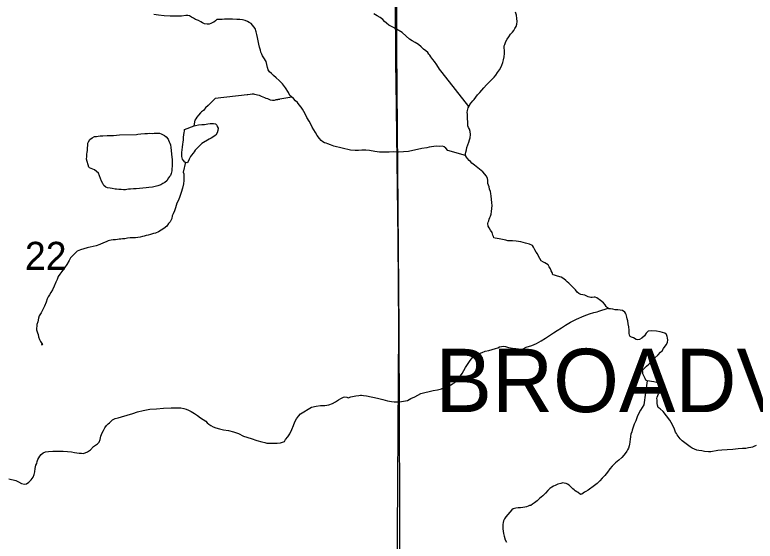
# Model space of a CAD drawing. Extents: x 2010165 to 2382125, y 1060529 to 1407316.
# Drawn here: x 2189541 to 2195389, y 1211343 to 1215496 of the extents above; entities that cross this region are included whole.
import ezdxf

# ---------------------------------------------------------------- set-up
doc = ezdxf.new("R2010")
doc.units = 0
for name, color, linetype in [('GM_X_Corporation_Text', 7, 'Continuous'), ('GM_X_Minor_Lake', 7, 'Continuous'), ('GM_X_Minor_River', 7, 'Continuous'), ('GM_X_Section', 7, 'Continuous'), ('GM_X_Section_Text', 7, 'Continuous'), ('GM_X_State_Route', 7, 'Continuous')]:
    doc.layers.add(name, color=color, linetype=linetype)

msp = doc.modelspace()

# ---------------------------------------------------------------- linework, layer by layer
at = {"layer": 'GM_X_Minor_Lake'}
for points in [[(2191077.5, 1214514.5), (2191017.7, 1214480.5), (2190998.2, 1214459.9), (2190986.4, 1214449.6), (2190976.7, 1214439.3), (2190967, 1214426.9), (2190957.3, 1214414.7), (2190949.5, 1214404.4), (2190936, 1214388), (2190930.2, 1214377.8), (2190918.7, 1214357.4), (2190911.2, 1214339.1), (2190901.5, 1214328.9), (2190883.3, 1214334.4), (2190872.9, 1214346.2), (2190864.6, 1214358), (2190860, 1214377.9), (2190859.7, 1214390), (2190861.2, 1214408.1), (2190862.6, 1214430.2), (2190866, 1214452.4), (2190869.4, 1214474.6), (2190871, 1214490.7), (2190872.5, 1214508.8), (2190874, 1214528.9), (2190877.4, 1214551.1), (2190879, 1214565.2), (2190880.7, 1214579.3), (2190882.3, 1214591.4), (2190957.8, 1214619.5)], [(2190957.8, 1214619.5), (2190967.7, 1214623.7), (2190991.6, 1214628.4), (2191017.6, 1214631.1), (2191039.7, 1214631.6), (2191053.6, 1214634), (2191065.7, 1214634.3), (2191085.6, 1214636.9), (2191101.7, 1214637.3), (2191111.7, 1214637.6), (2191125.8, 1214635.9), (2191136.1, 1214624.1), (2191140.4, 1214614.2), (2191146.8, 1214600.3), (2191145.3, 1214582.2), (2191139.7, 1214564), (2191128.2, 1214545.6), (2191092.7, 1214522.6), (2191077.5, 1214514.5)], [(2190125, 1214293.3), (2190106.6, 1214358.1), (2190110.1, 1214378.3), (2190111.5, 1214398.4), (2190113.2, 1214410.5), (2190114.7, 1214428.6), (2190119.3, 1214482.9), (2190123, 1214493.1), (2190134.5, 1214511.4), (2190152.3, 1214523.9), (2190170, 1214534.4), (2190186, 1214536.9), (2190200, 1214539.3), (2190215.9, 1214541.7), (2190236, 1214542.2), (2190270, 1214543.1), (2190296.1, 1214543.8), (2190322.1, 1214544.5), (2190344.2, 1214545.1), (2190368.2, 1214547.7), (2190503.5, 1214552.5)], [(2190503.5, 1214552.5), (2190512.4, 1214553.5), (2190536.4, 1214556.1), (2190568.4, 1214559), (2190588.4, 1214559.5), (2190606.4, 1214562), (2190626.5, 1214560.5), (2190642.5, 1214561), (2190658.6, 1214561.4), (2190674.6, 1214561.8), (2190684.6, 1214562.1), (2190696.8, 1214556.4), (2190713.1, 1214548.8), (2190723.2, 1214543), (2190737.5, 1214533.3), (2190752, 1214515.6), (2190756.3, 1214505.7), (2190760.6, 1214493.8), (2190767, 1214481.9), (2190771.3, 1214470), (2190773.9, 1214448), (2190782, 1214371.9), (2190784.5, 1214353.9), (2190785, 1214333.8), (2190785.5, 1214315.8), (2190783.9, 1214299.7), (2190782.4, 1214283.6), (2190780.8, 1214265.4), (2190779.2, 1214253.4), (2190775.4, 1214243.2), (2190769.8, 1214229), (2190764.1, 1214218.8), (2190756.3, 1214208.6), (2190742.9, 1214186.1), (2190727.2, 1214173.7), (2190711.4, 1214165.2), (2190693.6, 1214154.7), (2190669.8, 1214146.1), (2190649.8, 1214141.5), (2190630, 1214135), (2190600, 1214132.2), (2190580, 1214129.6), (2190552, 1214126.9), (2190526, 1214124.2), (2190499.9, 1214123.5), (2190477.9, 1214122.9), (2190455.9, 1214120.3), (2190439.9, 1214119.9), (2190425.9, 1214117.6), (2190415.9, 1214115.3), (2190399.9, 1214114.9), (2190381.8, 1214116.4), (2190363.7, 1214117.9), (2190345.6, 1214119.5), (2190333.6, 1214121.1), (2190309.4, 1214124.5), (2190293.3, 1214128.1), (2190273.1, 1214131.6), (2190261, 1214135.3), (2190244.6, 1214148.9), (2190236.1, 1214164.8), (2190225.6, 1214182.6), (2190210.4, 1214226.3), (2190201.9, 1214246.2), (2190171.1, 1214271.5), (2190156.9, 1214279.1), (2190132.5, 1214288.5), (2190125, 1214293.3)]]:
    msp.add_lwpolyline(points, dxfattribs=at)
at = {"layer": 'GM_X_Minor_River'}
for points in [[(2191060.5, 1215421.3), (2191040.3, 1215424.8), (2191024.1, 1215432.4), (2191009.8, 1215440), (2190991.5, 1215451.6), (2190969.2, 1215459), (2190952.9, 1215468.6), (2190936.6, 1215478.2), (2190922.3, 1215487.9), (2190908.2, 1215491.5), (2190892.2, 1215491.1), (2190858.2, 1215486.2), (2190816.1, 1215485.1), (2190768, 1215485.8), (2190721.8, 1215488.6), (2190677.5, 1215493.5), (2190639.3, 1215498.5)], [(2193128.3, 1214773.3), (2192915.5, 1215040.4), (2192894.7, 1215068), (2192875.8, 1215101.6), (2192857.1, 1215127.3), (2192842.6, 1215142.9), (2192834.3, 1215152.8), (2192828, 1215164.6), (2192819.6, 1215176.5), (2192811.3, 1215186.3), (2192803, 1215198.1), (2192786.6, 1215211.7), (2192768.2, 1215225.3), (2192749.7, 1215242.9), (2192729.1, 1215262.4), (2192704.6, 1215277.8), (2192680.2, 1215291.3), (2192657.8, 1215304.7), (2192631.1, 1215326.1), (2192600.2, 1215357.4), (2192555.4, 1215382.3), (2192522.9, 1215399.6), (2192496.4, 1215414.9), (2192477.9, 1215430.5), (2192461.5, 1215444.1), (2192447, 1215459.8), (2192426.6, 1215473.3), (2192404.2, 1215486.8), (2192377.7, 1215502.1)], [(2193125.8, 1214606.3), (2193119.4, 1214620.2), (2193119.1, 1214632.2), (2193118.8, 1214642.2), (2193118.4, 1214656.3), (2193118, 1214670.3), (2193117.4, 1214692.4), (2193116.9, 1214712.5), (2193114.6, 1214724.4), (2193116.1, 1214740.6), (2193121.6, 1214760.8), (2193129.2, 1214775), (2193134.9, 1214789.2), (2193146.6, 1214801.6), (2193158.2, 1214815.9), (2193169.9, 1214828.3), (2193181.5, 1214844.7), (2193197, 1214863.1), (2193214.6, 1214881.7), (2193230.1, 1214900.2), (2193245.6, 1214920.6), (2193267.1, 1214943.3), (2193327.6, 1215003.1), (2193341.2, 1215019.5), (2193354.7, 1215040), (2193368.2, 1215060.4), (2193379.7, 1215078.8), (2193389.2, 1215099.1), (2193394.7, 1215119.3), (2193402.1, 1215139.6), (2193405.5, 1215163.8), (2193408.8, 1215190), (2193408.2, 1215214.1), (2193405.6, 1215234.1), (2193407.1, 1215252.2), (2193410.9, 1215262.3), (2193418.3, 1215284.6), (2193429.8, 1215303), (2193443.4, 1215321.4), (2193456.8, 1215341.8), (2193472.4, 1215358.3), (2193482.1, 1215372.6), (2193491.7, 1215386.9), (2193501.3, 1215403.2), (2193506.8, 1215421.4), (2193508.2, 1215443.6), (2193507.6, 1215467.6), (2193502.9, 1215491.6), (2193496.3, 1215515.5)], [(2193101.6, 1214386.8), (2192960.2, 1214425.2), (2192945.7, 1214442.9), (2192931.4, 1214454.6), (2192919.2, 1214458.3), (2192897.2, 1214457.7), (2192873.1, 1214459.1), (2192851.1, 1214456.5), (2192833.1, 1214454), (2192815.1, 1214451.5), (2192795.3, 1214445), (2192755.3, 1214439.9), (2192721.4, 1214433), (2192685.5, 1214424), (2192651.6, 1214417.1), (2192611.6, 1214414), (2192573.5, 1214413), (2192535.4, 1214414.1), (2192499.3, 1214413.1), (2192461.3, 1214412.1), (2192421.1, 1214413.1), (2192384.9, 1214418.1), (2192342.6, 1214425), (2192312.5, 1214428.2), (2192282.4, 1214427.5), (2192256.4, 1214424.8), (2192228.3, 1214424), (2192192.1, 1214429.1), (2192060.9, 1214459.8), (2192034.6, 1214471.1), (2192014.3, 1214478.6), (2192000.2, 1214482.3), (2191988.1, 1214486), (2191973.8, 1214493.6), (2191961.5, 1214503.3), (2191947, 1214521), (2191930.4, 1214542.7), (2191915.7, 1214566.4), (2191903.1, 1214588.1), (2191890.5, 1214609.9), (2191879.8, 1214631.7), (2191865.2, 1214655.4), (2191848.3, 1214685.1), (2191837.7, 1214708.9), (2191825, 1214732.6), (2191812.5, 1214750.4), (2191802, 1214766.2), (2191787.5, 1214785.9), (2191772.9, 1214803.6), (2191758.5, 1214817.2), (2191742, 1214834.9), (2191725.6, 1214848.5), (2191713.3, 1214860.2), (2191702.6, 1214884), (2191679.6, 1214919.6), (2191654.7, 1214951), (2191629.9, 1214976.5), (2191605.3, 1214997.9), (2191584.7, 1215017.5), (2191568.2, 1215033.1), (2191553.8, 1215046.8), (2191543.4, 1215062.5), (2191536.9, 1215080.4), (2191532.3, 1215102.4), (2191525.6, 1215126.3), (2191508.8, 1215156), (2191498.3, 1215171.8), (2191491.9, 1215185.7), (2191485.5, 1215201.6), (2191481.1, 1215217.5), (2191474.4, 1215239.4), (2191469.7, 1215265.4), (2191463, 1215291.3), (2191458.3, 1215317.3), (2191453.6, 1215341.3), (2191447.1, 1215361.2), (2191440.4, 1215387.1), (2191407.2, 1215426.4), (2191392.9, 1215436.1), (2191378.7, 1215443.7), (2191360.4, 1215451.3), (2191340.2, 1215456.8), (2191318.1, 1215458.2), (2191294.1, 1215457.6), (2191261.9, 1215460.7), (2191231.8, 1215461.9), (2191197.8, 1215461), (2191179.8, 1215458.6), (2191159.7, 1215460), (2191145.7, 1215459.7), (2191135.7, 1215457.4), (2191125.9, 1215447.1), (2191114.1, 1215438.8), (2191104.2, 1215434.5), (2191090.4, 1215426.1), (2191076.5, 1215421.7), (2191060.5, 1215421.3)], [(2191376.3, 1214863.4), (2191124.4, 1214834.7), (2191110.7, 1214822.3), (2191093.2, 1214803.7), (2191069.7, 1214781), (2191048.2, 1214762.4), (2191032.7, 1214741.9), (2191017, 1214729.4), (2191007.2, 1214721.1), (2190991.6, 1214704.7), (2190980, 1214688.3), (2190972.3, 1214676.1), (2190962.5, 1214665.8), (2190955.9, 1214618.8)], [(2191729.9, 1214844.9), (2191601.9, 1214825.2), (2191633.9, 1214830), (2191601.9, 1214825.2), (2191590, 1214820.8), (2191584, 1214820.7), (2191576, 1214820.5), (2191561.9, 1214822.1), (2191539.6, 1214831.6), (2191527.5, 1214835.2), (2191517.3, 1214841), (2191503.1, 1214846.6), (2191491, 1214850.3), (2191474.7, 1214857.9), (2191458.6, 1214861.5), (2191438.4, 1214867), (2191428.3, 1214868.8), (2191416.3, 1214868.5), (2191400.3, 1214866), (2191382.3, 1214865.6), (2191380.3, 1214863.5), (2191376.3, 1214863.4)], [(2194126.4, 1213267.3), (2194116.4, 1213267.1), (2194102.4, 1213264.7), (2194090.3, 1213266.4), (2194070.1, 1213271.9), (2194043.8, 1213283.2), (2194011.5, 1213290.4), (2193997.3, 1213298), (2193983, 1213307.7), (2193970.5, 1213325.4), (2193960.1, 1213337.2), (2193945.7, 1213350.9), (2193931.3, 1213364.6), (2193916.9, 1213378.2), (2193904.5, 1213390), (2193894.2, 1213399.7), (2193877.9, 1213411.4), (2193855.5, 1213424.8), (2193827.2, 1213434.1), (2193804.9, 1213441.6), (2193790.8, 1213443.2), (2193784.3, 1213463.1), (2193777.9, 1213477), (2193773.5, 1213490.9), (2193763, 1213506.7), (2193752.6, 1213522.5), (2193740.3, 1213532.2), (2193728.1, 1213537.9), (2193715.9, 1213543.6), (2193697.6, 1213555.2), (2193687, 1213573), (2193676.5, 1213592.8), (2193670, 1213608.7), (2193659.6, 1213622.4), (2193649.1, 1213642.3), (2193638.5, 1213662.1), (2193630.1, 1213675.9), (2193605.8, 1213687.3), (2193575.5, 1213694.5), (2193539.2, 1213703.6), (2193500.9, 1213708.6), (2193472.7, 1213711.9), (2193458.7, 1213711.5), (2193448.7, 1213711.3), (2193436.6, 1213712.9), (2193420.4, 1213718.6), (2193394.2, 1213723.9), (2193366, 1213729.2), (2193335.8, 1213732.4), (2193325.7, 1213736.1), (2193321.4, 1213746.1), (2193317.1, 1213758), (2193310.5, 1213777.9), (2193298, 1213797.6), (2193287.5, 1213815.4), (2193281.1, 1213829.3), (2193278.5, 1213849.3), (2193280.3, 1213859.4), (2193284, 1213869.6), (2193287.6, 1213883.7), (2193293.3, 1213897.9), (2193299, 1213908.1), (2193304.6, 1213922.3), (2193306.1, 1213944.4), (2193309.4, 1213968.6), (2193310.8, 1213990.7), (2193310.2, 1214012.8), (2193307.5, 1214040.8), (2193304.8, 1214064.9), (2193302.3, 1214084.9), (2193297.8, 1214102.8), (2193291.3, 1214120.7), (2193286.8, 1214138.7), (2193282.4, 1214150.6), (2193278.1, 1214164.6), (2193277.7, 1214176.6), (2193277.4, 1214190.6), (2193275, 1214204.6), (2193266.5, 1214222.5), (2193237.5, 1214255.8), (2193186.2, 1214298.7), (2193171.9, 1214308.3), (2193161.7, 1214316.1), (2193151.4, 1214325.9), (2193141, 1214337.6), (2193130.8, 1214347.4), (2193116.3, 1214363.1), (2193108, 1214372.9), (2193101.6, 1214386.8), (2193101.3, 1214398.8), (2193102.9, 1214412.9), (2193108.4, 1214431.1), (2193112, 1214449.3), (2193119.4, 1214469.6), (2193126.9, 1214491.9), (2193132.4, 1214508.1), (2193138, 1214526.3), (2193139.3, 1214552.4), (2193136.7, 1214574.4), (2193132.2, 1214592.4), (2193125.8, 1214606.3)], [(2190890.7, 1214332.1), (2190871.4, 1214253.8), (2190875.7, 1214241.8), (2190876.1, 1214229.8), (2190876.3, 1214219.8), (2190876.8, 1214201.7), (2190875.2, 1214187.6), (2190873.9, 1214161.5), (2190866.8, 1214127.2), (2190855.6, 1214094.7), (2190844.5, 1214062.3), (2190833.2, 1214033.9), (2190821.8, 1214009.5), (2190816.3, 1213991.3), (2190810.8, 1213973.1), (2190801.4, 1213948.8), (2190792, 1213926.4), (2190784.4, 1213910.2), (2190780.9, 1213890), (2190767.6, 1213863.6), (2190756, 1213849.2), (2190742.5, 1213828.7), (2190718.9, 1213810.1), (2190697.3, 1213795.4), (2190675.5, 1213784.8), (2190653.7, 1213774.2), (2190635.8, 1213769.7), (2190613.9, 1213763.1), (2190594.1, 1213756.6), (2190578.1, 1213754.1), (2190564.2, 1213749.8), (2190550.2, 1213747.4), (2190530.3, 1213740.8), (2190512.3, 1213738.4), (2190494.4, 1213735.9), (2190468.3, 1213737.2), (2190452.2, 1213736.8), (2190432.2, 1213734.2), (2190410.3, 1213729.6), (2190392.3, 1213727.2), (2190378.4, 1213724.8), (2190366.3, 1213724.5), (2190352.3, 1213724.1), (2190336.3, 1213721.7), (2190318.3, 1213719.2), (2190302.4, 1213716.8), (2190288.4, 1213714.4), (2190278.4, 1213712.1), (2190262.6, 1213705.7), (2190240.7, 1213697.1), (2190213, 1213684.3), (2190185.2, 1213673.5), (2190159.3, 1213666.8), (2190137.4, 1213662.2), (2190123.4, 1213659.8), (2190113.5, 1213657.6), (2190059.7, 1213642.1), (2190045.9, 1213635.7), (2190034, 1213631.4), (2190024.2, 1213621.1), (2190010.6, 1213606.7), (2189994.9, 1213592.2), (2189981.3, 1213577.8), (2189971.8, 1213557.5), (2189952.6, 1213526.8), (2189933.3, 1213498.2), (2189914, 1213471.6), (2189896.5, 1213449.1), (2189885, 1213430.7), (2189875.6, 1213408.4), (2189866.1, 1213386), (2189853, 1213353.6), (2189839.7, 1213327.1), (2189826.2, 1213304.7), (2189814.7, 1213286.3), (2189805.1, 1213270), (2189797.5, 1213253.7), (2189788.1, 1213229.4), (2189775, 1213196.9), (2189759.8, 1213166.4), (2189748.3, 1213144), (2189734.9, 1213121.6), (2189729.4, 1213101.3), (2189722.2, 1213073.1), (2189714.7, 1213052.8), (2189711.8, 1213010.5), (2189720.5, 1212986.7), (2189724.8, 1212974.8), (2189729.4, 1212954.8), (2189735.9, 1212934.9), (2189744.4, 1212917.1), (2189754.8, 1212903.3), (2189761.1, 1212893.4), (2189753.1, 1212893.2), (2189761.1, 1212893.4)], [(2194989.4, 1212051.2), (2194967.3, 1212054.7), (2194945.1, 1212058.1), (2194927, 1212061.6), (2194908.7, 1212069.2), (2194890.5, 1212076.7), (2194874.1, 1212088.3), (2194853.6, 1212103.9), (2194833.2, 1212119.4), (2194812.7, 1212134.9), (2194796.2, 1212150.6), (2194781.7, 1212170.2), (2194773.3, 1212182.1), (2194767.1, 1212191.9), (2194760.7, 1212203.8), (2194752, 1212227.7), (2194737.1, 1212261.4), (2194714.1, 1212297), (2194689.1, 1212332.4), (2194662.1, 1212365.9), (2194637.5, 1212387.3), (2194623.2, 1212397), (2194616.6, 1212416.9), (2194614.3, 1212428.9), (2194613.9, 1212442.9), (2194613.5, 1212456.9), (2194613.2, 1212469), (2194614.9, 1212479.1), (2194620.6, 1212491.2), (2194626.2, 1212505.5), (2194639.7, 1212525.9), (2194643.2, 1212546.1), (2194638.7, 1212562), (2194630.3, 1212577.8), (2194622, 1212589.7), (2194611.8, 1212595.4), (2194587.6, 1212598.8), (2194535.3, 1212607.5), (2194525.1, 1212613.2), (2194520.7, 1212627.2), (2194512.2, 1212643), (2194501.7, 1212662.8), (2194501.2, 1212678.9), (2194499, 1212688.8), (2194506.7, 1212701.1), (2194516.4, 1212711.4), (2194530.1, 1212723.8), (2194549.7, 1212740.4), (2194573.2, 1212761.1), (2194592.6, 1212787.7), (2194622, 1212812.5), (2194641.4, 1212833.1), (2194653.1, 1212845.5), (2194664.7, 1212863.8), (2194678.3, 1212880.3), (2194687.9, 1212894.6), (2194697.5, 1212912.9), (2194699, 1212929), (2194696.5, 1212947), (2194694.3, 1212957), (2194687.8, 1212972.9), (2194675.5, 1212984.6), (2194657.3, 1212990.1), (2194639.1, 1212993.7), (2194608.9, 1212998.9), (2194566.7, 1213001.8), (2194544.7, 1212999.2), (2194529.1, 1212982.8), (2194515.6, 1212964.3), (2194494, 1212945.7), (2194474.3, 1212935.1), (2194460.4, 1212930.8), (2194450.2, 1212934.5), (2194427.8, 1212948), (2194411.6, 1212953.6), (2194401.5, 1212957.3), (2194395.1, 1212969.2), (2194394.7, 1212985.2), (2194394.1, 1213007.3), (2194391.4, 1213033.3), (2194386.8, 1213057.3), (2194384.1, 1213081.3), (2194377.7, 1213097.2), (2194375.3, 1213111.2), (2194368.7, 1213131.1), (2194364.4, 1213141.1), (2194360.2, 1213151), (2194341.8, 1213162.6), (2194323.7, 1213166.1), (2194303.6, 1213167.6), (2194283.5, 1213169.1), (2194265.3, 1213172.6), (2194245.2, 1213176.1), (2194233.2, 1213175.8), (2194222.9, 1213183.5), (2194212.6, 1213195.3), (2194204.2, 1213207.1), (2194189.8, 1213222.8), (2194167.2, 1213242.3), (2194138.6, 1213261.6), (2194126.4, 1213267.3)], [(2193060.4, 1212647), (2193073.9, 1212665.4), (2193087.3, 1212689.8), (2193100.6, 1212714.3), (2193116.1, 1212736.8), (2193131.5, 1212759.3), (2193147, 1212779.8), (2193160.6, 1212796.2), (2193180.4, 1212806.7), (2193194.2, 1212815.1), (2193212, 1212823.6), (2193231.8, 1212832.2), (2193257.6, 1212840.9), (2193285.5, 1212847.6), (2193311.4, 1212854.3), (2193337.3, 1212863.1), (2193355.1, 1212869.6), (2193369, 1212875.9), (2193400.9, 1212882.8), (2193417, 1212879.2), (2193441.3, 1212871.8), (2193471.5, 1212866.6), (2193499.7, 1212863.3), (2193515.8, 1212861.7), (2193531.9, 1212856.1), (2193555.9, 1212860.8), (2193579.6, 1212873.4), (2193625.4, 1212886.7), (2193663, 1212903.8), (2193698.5, 1212924.8), (2193732.1, 1212945.7), (2193763.6, 1212966.6), (2193795.1, 1212985.5), (2193824.7, 1213004.4), (2193858.2, 1213027.3), (2193891.7, 1213048.3), (2193931.2, 1213071.4), (2193976.7, 1213094.7), (2194038.1, 1213120.4), (2194079.8, 1213135.6), (2194115.6, 1213146.6), (2194141.5, 1213153.3), (2194153.4, 1213157.6), (2194226.5, 1213180.8)], [(2190334.3, 1212310.2), (2190358.2, 1212316.8), (2190384.1, 1212323.5), (2190473.6, 1212350), (2190509.4, 1212363), (2190555.2, 1212374.2), (2190607.1, 1212383.6), (2190661.1, 1212387.1), (2190715.1, 1212392.5), (2190777.2, 1212394.1), (2190817.3, 1212395.2), (2190851.4, 1212394.1), (2190877.6, 1212390.7), (2190895.8, 1212385.2), (2190912, 1212377.6), (2190934.4, 1212366.1), (2190960.9, 1212350.8), (2190983.4, 1212333.3), (2191007.9, 1212315.9), (2191028.3, 1212302.4), (2191048.8, 1212288.8), (2191061.1, 1212277.1), (2191073.5, 1212265.4), (2191089.8, 1212255.8), (2191108.1, 1212246.2), (2191130.4, 1212236.8), (2191158.6, 1212229.5), (2191190.9, 1212222.3), (2191229.2, 1212215.3), (2191267.6, 1212206.3), (2191308.1, 1212191.3), (2191348.7, 1212170.3), (2191409.4, 1212151.8), (2191453.9, 1212136.9), (2191492.3, 1212125.9), (2191516.5, 1212120.5), (2191530.6, 1212116.8), (2191546.7, 1212115.2), (2191566.8, 1212115.8), (2191588.8, 1212116.3), (2191612.9, 1212117), (2191638.8, 1212119.7), (2191656.8, 1212124.2), (2191670.6, 1212130.6), (2191680.3, 1212144.8), (2191697.8, 1212165.4), (2191713.2, 1212189.9), (2191728.3, 1212224.4), (2191741.4, 1212256.9), (2191752.7, 1212283.3), (2191766.1, 1212307.7), (2191781.6, 1212328.2), (2191797.1, 1212348.7), (2191885.9, 1212401.2), (2191921.8, 1212408.2), (2191955.8, 1212413.1), (2191989.8, 1212414), (2192021.8, 1212418.9), (2192051.6, 1212429.7), (2192075.3, 1212442.4), (2192097, 1212457), (2192116.7, 1212469.5), (2192136.5, 1212478.1), (2192148.4, 1212482.4), (2192162.5, 1212478.8), (2192174.7, 1212473.1), (2192196.6, 1212481.7), (2192220.5, 1212486.3), (2192234.5, 1212488.7), (2192258.4, 1212493.4), (2192270.4, 1212493.7), (2192280.4, 1212493.9), (2192296.5, 1212492.4), (2192318.7, 1212488.9), (2192355, 1212481.8), (2192383.2, 1212476.6), (2192415.5, 1212469.4), (2192447.8, 1212460.2), (2192486.1, 1212451.2), (2192516.4, 1212445.9), (2192538.5, 1212442.5), (2192556.5, 1212443), (2192580.6, 1212443.6), (2192610.6, 1212446.4), (2192642.5, 1212453.3), (2192670.2, 1212468.1), (2192699.9, 1212480.9), (2192723.6, 1212493.6), (2192749.3, 1212508.3), (2192779.1, 1212517.1), (2192813, 1212524), (2192846.9, 1212530.9), (2192878.9, 1212535.8), (2192910.7, 1212544.7), (2192942.5, 1212557.5), (2192972.2, 1212568.4), (2192997.9, 1212583.1), (2193017.6, 1212595.6), (2193035.1, 1212616.2), (2193046.8, 1212628.6), (2193060.4, 1212647)], [(2194535.3, 1212607.5), (2194508.3, 1212418), (2194496.8, 1212397.6), (2194483.3, 1212377.2), (2194471.8, 1212358.8), (2194456.7, 1212324.3), (2194445.5, 1212291.9), (2194434.2, 1212265.5), (2194424.8, 1212241.2), (2194417.4, 1212218.9), (2194413.8, 1212204.7), (2194406.3, 1212186.5), (2194404.6, 1212172.4), (2194402.9, 1212162.3), (2194401.2, 1212150.2), (2194399.9, 1212124.1), (2194396.4, 1212107.9), (2194394.7, 1212095.8), (2194389.2, 1212077.6), (2194381.5, 1212063.3), (2194375.8, 1212053.2), (2194362.2, 1212034.7), (2194350.6, 1212020.4), (2194335, 1212003.9), (2194311.5, 1211983.2), (2194286, 1211960.4), (2194260.6, 1211935.7), (2194241.2, 1211913.1), (2194221.8, 1211888.5), (2194202.5, 1211859.9), (2194181, 1211839.2), (2194161.5, 1211818.6), (2194142, 1211798.1), (2194120.4, 1211781.4), (2194069.3, 1211745.9), (2194051.5, 1211735.4), (2194039.6, 1211729.1), (2194020, 1211714.5), (2194010, 1211712.3), (2193991.6, 1211725.8), (2193979.4, 1211731.5), (2193967.2, 1211739.2), (2193958.9, 1211749.1), (2193948.6, 1211756.8), (2193919.8, 1211784.2), (2193905.5, 1211793.8), (2193895.4, 1211797.6), (2193881.3, 1211801.2), (2193869.2, 1211802.9), (2193853.3, 1211798.5), (2193831.4, 1211791.9), (2193809.6, 1211783.3), (2193795.7, 1211776.9), (2193781.9, 1211768.5), (2193768.1, 1211758.1), (2193752.5, 1211743.6), (2193733, 1211721.1), (2193711.5, 1211700.4), (2193686, 1211679.6), (2193666.5, 1211661.1), (2193646.9, 1211644.5), (2193631.1, 1211634), (2193617.3, 1211625.6), (2193605.3, 1211623.3), (2193595.4, 1211619.1), (2193581.6, 1211612.7), (2193569.6, 1211610.3), (2193553.6, 1211607.9), (2193535.6, 1211605.4), (2193517.6, 1211604.9), (2193497.6, 1211602.4), (2193477.7, 1211597.9), (2193465.8, 1211591.5), (2193419.2, 1211536.1), (2193409.6, 1211519.8), (2193402, 1211503.5), (2193398.4, 1211489.4), (2193394.8, 1211475.2), (2193395.3, 1211457.2), (2193395.8, 1211439.1), (2193398.3, 1211421.1), (2193400.7, 1211403.1), (2193407.3, 1211383.2), (2193414.1, 1211353.3), (2193424.6, 1211335.5)], [(2189492.9, 1211834.3), (2189549.4, 1211821.7), (2189569.8, 1211810.2), (2189594.2, 1211796.8), (2189618.4, 1211793.4), (2189634.3, 1211795.8), (2189652.1, 1211808.4), (2189669.6, 1211826.9), (2189685.1, 1211847.4), (2189694.6, 1211867.7), (2189700, 1211889.9), (2189703.3, 1211916.1), (2189708.6, 1211942.4), (2189714.2, 1211956.6), (2189717.8, 1211972.7), (2189723.4, 1211986.9), (2189731.1, 1211999.2), (2189738.8, 1212013.4), (2189750.4, 1212027.8), (2189766.1, 1212040.2), (2189784, 1212046.7), (2189808, 1212049.4), (2189842, 1212052.3), (2189876, 1212053.2), (2189922.2, 1212052.4), (2189958.3, 1212051.3), (2189988.5, 1212048.1), (2190012.7, 1212042.7), (2190030.8, 1212039.2), (2190050.9, 1212037.7), (2190069, 1212036.2), (2190081.1, 1212034.5), (2190097, 1212038.9), (2190116.8, 1212047.5), (2190140.4, 1212064.2), (2190163.8, 1212088.9), (2190193.4, 1212109.7), (2190207, 1212124.1), (2190214.5, 1212144.4), (2190221.7, 1212172.7), (2190231.1, 1212197), (2190240.6, 1212215.4), (2190252.1, 1212237.8), (2190265.6, 1212256.2), (2190279.3, 1212268.6), (2190289.1, 1212276.9), (2190312.6, 1212299.6), (2190334.3, 1212310.2)], [(2195397.2, 1212098.1), (2195379.4, 1212089.6), (2195367.5, 1212085.3), (2195353.6, 1212080.9), (2195335.6, 1212078.4), (2195315.7, 1212073.9), (2195287.6, 1212073.1), (2195253.6, 1212070.2), (2195211.6, 1212067.1), (2195167.5, 1212063.9), (2195125.5, 1212060.8), (2195093.5, 1212058), (2195037.6, 1212048.5), (2195019.6, 1212048), (2194989.4, 1212051.2)]]:
    msp.add_lwpolyline(points, dxfattribs=at)
at = {"layer": 'GM_X_Section'}
msp.add_lwpolyline([(2192553.9, 1216366.5), (2192555.1, 1215228.6), (2192573.5, 1213021.2), (2192581.3, 1210907.7), (2187059.5, 1210937.2), (2186961.3, 1216421.1)], close=True, dxfattribs=at)
at = {"layer": 'GM_X_State_Route'}
for points in [[(2192552.9, 1214967.7), (2192551.2, 1215108.4), (2192546.4, 1216193.7), (2192535.4, 1217651.9)], [(2192591.2, 1209073.3), (2192590.7, 1209504.2), (2192561.2, 1211005.5), (2192573.3, 1213021.3), (2192568.3, 1213719.8), (2192552.9, 1214967.7)]]:
    msp.add_lwpolyline(points, dxfattribs=at)

# ---------------------------------------------------------------- texts
at = {"layer": 'GM_X_Corporation_Text'}
msp.add_text('BROADVIEW HEIGHTS', height=500, rotation=0.00001, dxfattribs=at).set_placement((2192864, 1212361.1))
at = {"layer": 'GM_X_Section_Text'}
msp.add_text('22', height=221, rotation=0.00001, dxfattribs=at).set_placement((2189621.2, 1213483.6))

doc.saveas('drawing.dxf')
